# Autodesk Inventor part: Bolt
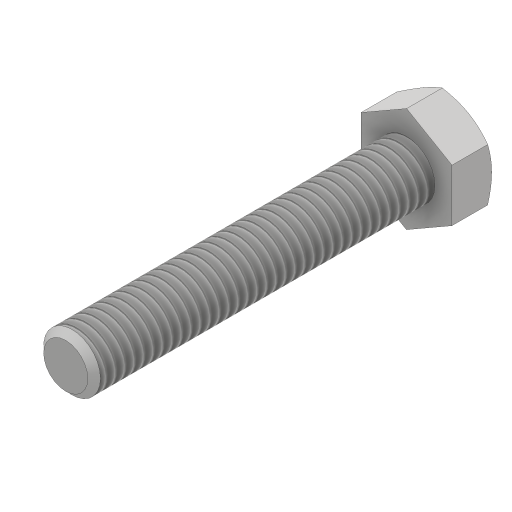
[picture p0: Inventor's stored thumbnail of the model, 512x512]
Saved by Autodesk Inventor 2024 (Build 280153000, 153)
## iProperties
Created: 2016-05
Part Number: Bolt
Material: Generic
Document SubType Name: Modeling
Designer: CADCIM
Density: 1 g/cm^3
Appearance: Default
Author: CADCIM
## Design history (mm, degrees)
sketch "Sketch1"
  geometry: L1 (3.604, -2.072)-(0.007, -4.157); L2 (0.007, -4.157)-(-3.596, -2.085); L3 (-3.596, -2.085)-(-3.604, 2.072); L4 (-3.604, 2.072)-(-0.007, 4.157); L5 (-0.007, 4.157)-(3.596, 2.085); L6 (3.596, 2.085)-(3.604, -2.072); 2 further points
  constraints: 12 end point, 1 coincident, 13 other
  dimensions: "d0" = 7.2 distance between parallel lines of L3 L6
extrude "Extrusion1" new body sketch "Sketch1" distance "d1" = 3.15; taper "d2" = 0 deg
sketch "Sketch2"
  geometry: C1 r 2.25 at (0, 0); 1 further point
  constraints: 1 centre point, 1 coincident
  dimensions: "d3" = 4.5 diameter of C1
extrude "Extrusion2" join sketch "Sketch2" distance "d4" = 27; taper "d5" = 0 deg
thread "Thread1" dims "d6" = 10, "d7" = 0
chamfer "Chamfer1" distance "d8" = 0.5; stored, may be unused: second distance "d9" = 2, angle "d10" = 45 deg
sketch "Sketch3"
  geometry: L1 (0.007, -4.157)-(3.604, -2.072) reference; C1 r 3.6 at (0, 0); 1 further point
  constraints: 1 centre point, 1 coincident, 1 tangent
extrude "Extrusion3" sketch "Sketch3" distance "d11" = 41; taper "d12" = 60 deg
body "Solid1"
